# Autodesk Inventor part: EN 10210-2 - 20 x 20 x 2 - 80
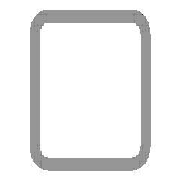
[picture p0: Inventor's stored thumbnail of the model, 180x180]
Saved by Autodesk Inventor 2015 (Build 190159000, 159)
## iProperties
Created: 2015-05
Part Number: EN 10210-2 - 20 x 20 x 2 - 80
Material: Steel, Mild
Description: Tube
Document SubType Name: Modeling
Standard: DIN
Designer: TREINA6
Standard Revision: 1997
Standards Organization: DIN
Language: en-US
Size Designation: 20 x 20 x 2
Categories: <MemberInstance><Categories><Category DisplayName="Structural Shapes" InternalName="089c4875-fa83-4c05-b084-43b9cc11f5ed" Mnemonic="GRDR"><CategoryParameter Dis
Stock Number: 20 x 20 x 2
Density: 7.85 g/cm^3
Appearance: Semi-Polished
IsCustomPart: 1
G_L: 80,000 mm
G_W: 20,000 mm
G_H: 20,000 mm
+FB05D694-CED5-4101-8B66-83472582E2F0+CUTDETAIL1: Cut
_CCFamilyMember: 1
_CCFamilyDisplayName: DIN EN 10210-2 (Square) - Tube
_FrameMemberDoc: Frame Member File
_Version: 15.0.0
_GetPNFromCC: 1
Author: TREINA6
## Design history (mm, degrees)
node "Start plane"
node "End plane"
sketch "Sketch"
  geometry: L1 (-10, -7)-(-10, 7); L2 (-7, 10)-(7, 10); L3 (10, 7)-(10, -7); L4 (7, -10)-(-7, -10); L5 (-7, 8)-(7, 8); L6 (8, 7)-(8, -7); L7 (7, -8)-(-7, -8); L8 (-8, -7)-(-8, 7); L9 (0, 14.87)-(0, -14.87) reference; L10 (-14.87, 0)-(14.87, 0) reference; A1 r 3 centre (-7, -7) between (-10, -7) and (-7, -10); A2 r 3 centre (-7, 7) between (-7, 10) and (-10, 7); A3 r 3 centre (7, 7) between (10, 7) and (7, 10); A4 r 3 centre (7, -7) between (7, -10) and (10, -7); A5 r 1 centre (-7, 7) between (-7, 8) and (-8, 7); A6 r 1 centre (7, 7) between (8, 7) and (7, 8); A7 r 1 centre (7, -7) between (7, -8) and (8, -7); A8 r 1 centre (-7, -7) between (-8, -7) and (-7, -8)
  constraints: 16 end point, 16 point on circle, 8 centre point, 8 tangent, 4 parallel, 3 equal radius, 2 perpendicular, 7 other
  dimensions: "d7" = 3 radius of A1 (= G_IR); "d10" = 20 distance between parallel lines of L2 L4 (= G_H); "d11" = 20 distance between parallel lines of L1 L3 (= G_W); "d12" = 2 distance between parallel lines of L3 L6 (= G_T); "d15" = 10 distance between parallel lines of L2 L10 (= 0.5 x d10); "d16" = 10 distance between parallel lines of L9 L3 (= 0.5 x d11)
extrude "Body" new body sketch "Sketch" stored distance "d3" = 80 (= G_L); taper "d4" = 0 deg
node "Driven Length"
  sketch "Sketch3"
    geometry: L1 (0, 0)-(10, 0) reference
    constraints: 2 end point, 1 horizontal
  workplane "Work Plane3"
  sketch "Sketch4"
    geometry: L1 (-2, 20)-(12, 20) reference; L2 (-2, 100)-(12, 100) reference
    dimensions: "d18" = 80 distance between parallel lines of L1 L2 (derived)
workplane "Work Plane4"
split "Split1"
body "Solid1"
other parameters: "G_W" = 20 [user parameter; used in 1 equation term], "G_H" = 20 [user parameter; used in 1 equation term], "G_T" = 2 [user parameter; used in 1 equation term], "G_IR" = 3 [user parameter; used in 1 equation term], "G_L" = 80 (= d18) [user parameter; used in 1 equation term], "G_OFFSET_END" = 0 [user parameter; used in 1 equation term], "d17" = 90 deg
